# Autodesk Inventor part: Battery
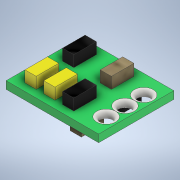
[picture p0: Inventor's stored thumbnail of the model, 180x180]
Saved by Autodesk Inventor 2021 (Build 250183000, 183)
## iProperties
Created: 2021-02
Part Number: Battery
Material: Generic
Document SubType Name: Modeling
Designer: callu
Density: 1 g/cm^3
Appearance: Default
Author: callu
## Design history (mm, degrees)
sketch "Sketch2"
  geometry: L1 (0, 0)-(12.3, 0); L2 (12.3, 0)-(12.3, -10); L3 (12.3, -10)-(0, -10); L4 (0, -10)-(0, 0)
  constraints: 8 end point, 2 parallel, 1 horizontal, 1 perpendicular
  dimensions: "d4" = 12.3 distance of L2.end L3.end; "d5" = 10 distance of L1.end L2.end
extrude "Extrusion2" new body sketch "Sketch2" distance "d6" = 1; taper "d7" = 0 deg
sketch "Sketch3"
  geometry: L1 (-10.8, 1)-(-9.3, 1); L2 (-9.3, 1)-(-9.3, 4); L3 (-9.3, 4)-(-10.8, 4); L4 (-10.8, 4)-(-10.8, 1); L5 (-12.3, 10)-(-12.3, 0) reference; L6 (-12.3, 0)-(0, 0) reference; L7 (-8.3, 1)-(-6.8, 1); L8 (-6.8, 1)-(-6.8, 4); L9 (-6.8, 4)-(-8.3, 4); L10 (-8.3, 4)-(-8.3, 1); L11 (-5.8, 1)-(-4.3, 1); L12 (-4.3, 1)-(-4.3, 4); L13 (-4.3, 4)-(-5.8, 4); L14 (-5.8, 4)-(-5.8, 1); L15 (-10.8, 6)-(-9.3, 6); L16 (-9.3, 6)-(-9.3, 9); L17 (-9.3, 9)-(-10.8, 9); L18 (-10.8, 9)-(-10.8, 6); L19 (0, 10)-(-12.3, 10) reference; L20 (-5.8, 6)-(-4.3, 6); L21 (-4.3, 6)-(-4.3, 9); L22 (-4.3, 9)-(-5.8, 9); L23 (-5.8, 9)-(-5.8, 6); L24 (0, 0)-(0, 10) reference; C1 r 0.75 at (-1.5, 2.5); C2 r 0.75 at (-1.5, 5); C3 r 0.75 at (-1.5, 7.5)
  constraints: 40 end point, 10 parallel, 5 horizontal, 5 perpendicular, 3 centre point
  dimensions: "d8" = 1.5 distance of L3.end L2.end; "d9" = 3 distance of L2.end L1.end; "d10" = 1.5 distance between parallel lines of L5 L4; "d11" = 1 distance between parallel lines of L6 L1; "d12" = 1.5 distance of L9.end L8.end; "d13" = 3 distance of L8.end L7.end; "d14" = 1 distance between parallel lines of L6 L7; "d15" = 1 distance between parallel lines of L10 L2; "d16" = 1.5 distance of L13.end L12.end; "d17" = 3 distance of L12.end L11.end; "d18" = 1 distance between parallel lines of L6 L11; "d19" = 1 distance between parallel lines of L14 L8; "d20" = 1.5 distance of L17.end L16.end; "d21" = 3 distance of L16.end L15.end; "d22" = 1 distance between parallel lines of L19 L17; "d23" = 1.5 distance between parallel lines of L5 L18; "d24" = 1 distance between parallel lines of L19 L22; "d25" = 3 distance of L22.end L20.start; "d26" = 3.5 distance between parallel lines of L16 L23; "d27" = 1.5 distance of L20.start L20.end; "d28" = 1.5 diameter of C1; "d29" = 1.5 diameter of C2; "d30" = 1.5 diameter of C3; "d31" = 1.5 distance from line of L24 C1.centre; "d32" = 1.5 distance from line of L24 C2.centre; "d33" = 1.5 distance from line of L24 C3.centre; "d34" = 2.5 distance from line of L19 C3.centre; "d35" = 2.5 distance from line of L6 C1.centre; "d36" = 5 distance from line of L19 C2.centre
extrude "Extrusion3" join sketch "Sketch3" distance "d37" = 1.5; taper "d38" = 0 deg
extrude "Extrusion4" cut sketch "Sketch3" distance "d39" = 2; taper "d40" = 0 deg
fillet "Fillet1" dims "d41" = 0.5
sketch "Sketch4"
  geometry: L1 (-11.3, -7.25)-(-6.3, -7.25); L2 (-6.3, -7.25)-(-6.3, -2.75); L3 (-6.3, -2.75)-(-11.3, -2.75); L4 (-11.3, -2.75)-(-11.3, -7.25); L5 (-12.3, 0)-(0, 0) reference; L6 (-12.3, -10)-(-12.3, 0) reference; L7 (-3.3, -9)-(-4.8, -9); L8 (-4.8, -9)-(-4.8, -6); L9 (-4.8, -6)-(-3.3, -6); L10 (-3.3, -6)-(-3.3, -9); L11 (0, -10)-(-12.3, -10) reference; L12 (-3.3, -4)-(-4.8, -4); L13 (-4.8, -4)-(-4.8, -1); L14 (-4.8, -1)-(-3.3, -1); L15 (-3.3, -1)-(-3.3, -4); 4 further points
  constraints: 24 end point, 6 parallel, 3 horizontal, 3 perpendicular
  dimensions: "d42" = 5 distance of L3.end L2.end; "d43" = 4.5 distance of L2.end L1.end; "d44" = 2.75 distance between parallel lines of L5 L3; "d45" = 1 distance between parallel lines of L6 L4; "d48" = 1.5 distance of L8.end L9.end; "d49" = 3 distance of L7.end L8.end; "d50" = 1.5 distance between parallel lines of L8 L2; "d51" = 1 distance between parallel lines of L11 L7; "d52" = 3 distance of L12.end L13.end; "d53" = 1.5 distance between parallel lines of L13 L2; "d54" = 1 distance between parallel lines of L5 L14; "d55" = 1.5 distance between parallel lines of L13 L15
extrude "Extrusion5" join sketch "Sketch4" distance "d46" = 1.5; taper "d47" = 0 deg
body "Solid2"
